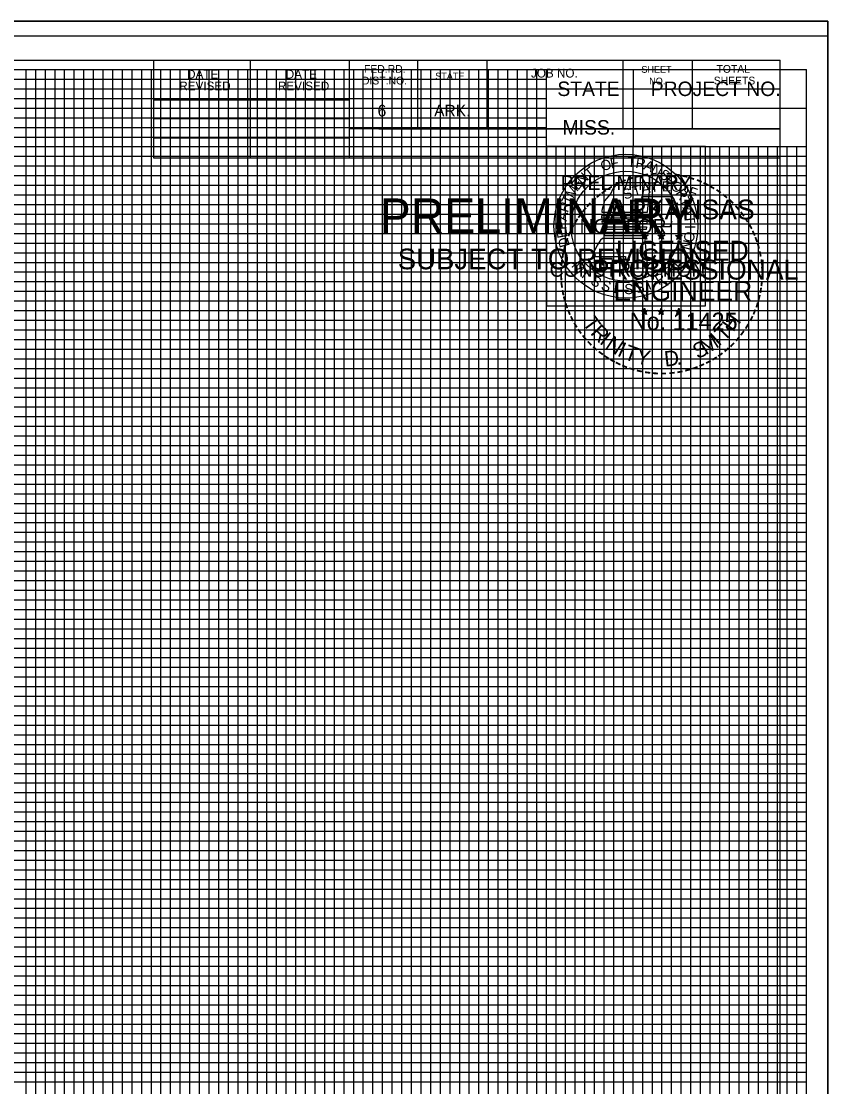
# Model space of a CAD drawing. Extents: x -10 to 342, y -5 to 215.
import ezdxf

# ---------------------------------------------------------------- set-up
doc = ezdxf.new("R2010")
doc.units = 0
for name, color, linetype in [('R_Border', 7, 'Continuous'), ('R_Border PE', 7, 'Continuous'), ('R_Border Prem', 7, 'Continuous'), ('R_No Plot', 7, 'Continuous'), ('SHEET_BORDER', 7, 'Continuous'), ('SHEET_LOGO', 7, 'Continuous'), ('SHEET_PLOTTING_SHAPE', 7, 'Continuous'), ('SHEET_PRELIM', 7, 'Continuous'), ('SHEET_PROJ_NUMBER', 7, 'Continuous'), ('XS_SHEET_MAJOR_GRIDS', 7, 'Continuous'), ('XS_SHEET_MEDIUM_GRIDS', 7, 'Continuous'), ('XS_SHEET_MINOR_GRIDS', 7, 'Continuous')]:
    doc.layers.add(name, color=color, linetype=linetype)

msp = doc.modelspace()

# ---------------------------------------------------------------- linework, layer by layer
at = {"layer": 'R_Border'}
for p, q in [((9.08, 210.98), (337.27, 210.98)), ((272.25, 200.79), (272.25, 210.98)), ((282.3, 200.79), (282.3, 210.98)), ((292.53, 210.98), (292.53, 200.79)), ((299.63, 210.98), (299.63, 203.83)), ((306.83, 210.98), (306.83, 203.83)), ((320.93, 210.98), (320.93, 203.83)), ((328.13, 210.98), (328.13, 203.83)), ((337.27, -0.89), (337.27, 210.98)), ((337.27, 207.95), (292.53, 207.95)), ((337.27, 207.97), (337.27, 207.97)), ((272.25, 206.84), (292.53, 206.84)), ((272.25, 204.92), (292.53, 204.92)), ((337.27, 203.83), (292.53, 203.83)), ((295.6, 203.83), (337.27, 203.83)), ((272.25, 202.92), (292.53, 202.92)), ((337.27, 200.79), (272.25, 200.79))]:
    msp.add_line(p, q, dxfattribs=at)
at = {"layer": 'R_Border PE'}
for p, q in [((322.82, 192.81), (323.18, 192.69)), ((322.82, 192.81), (323.09, 192.76)), ((322.82, 192.81), (323.07, 192.68)), ((322.96, 192.39), (323.18, 192.69)), ((322.96, 192.39), (323.09, 192.64)), ((322.96, 192.39), (323.18, 192.61)), ((323.18, 193.07), (323.14, 192.81)), ((323.18, 192.69), (323.18, 193.07)), ((323.18, 193.07), (323.24, 192.81)), ((323.55, 192.81), (323.18, 192.69)), ((323.41, 192.39), (323.18, 192.69)), ((323.41, 192.39), (323.18, 192.61)), ((323.55, 192.81), (323.25, 192.76)), ((323.41, 192.39), (323.26, 192.69)), ((323.55, 192.81), (323.33, 192.7)), ((324.56, 192.81), (324.92, 192.69)), ((324.56, 192.81), (324.82, 192.76)), ((324.56, 192.81), (324.8, 192.68)), ((324.69, 192.39), (324.92, 192.69)), ((324.69, 192.39), (324.82, 192.64)), ((324.69, 192.39), (324.92, 192.61)), ((324.92, 193.07), (324.88, 192.81)), ((324.92, 192.69), (324.92, 193.07)), ((324.92, 193.07), (324.97, 192.81)), ((325.28, 192.81), (324.92, 192.69)), ((325.14, 192.39), (324.92, 192.69)), ((325.14, 192.39), (324.92, 192.61)), ((325.28, 192.81), (324.98, 192.76)), ((325.14, 192.39), (325, 192.69)), ((325.28, 192.81), (325.07, 192.7)), ((326.39, 192.8), (326.75, 192.68)), ((326.39, 192.8), (326.65, 192.75)), ((326.39, 192.8), (326.63, 192.67)), ((326.53, 192.38), (326.75, 192.68)), ((326.53, 192.38), (326.66, 192.63)), ((326.53, 192.38), (326.75, 192.6)), ((326.75, 193.06), (326.71, 192.8)), ((326.75, 192.68), (326.75, 193.06)), ((326.75, 193.06), (326.8, 192.8)), ((327.11, 192.8), (326.75, 192.68)), ((326.97, 192.38), (326.75, 192.68)), ((326.97, 192.38), (326.75, 192.6)), ((327.11, 192.8), (326.81, 192.75)), ((326.97, 192.38), (326.83, 192.68)), ((327.11, 192.8), (326.9, 192.69)), ((322.82, 185), (323.18, 184.88)), ((322.82, 185), (323.08, 184.95)), ((322.82, 185), (323.06, 184.87)), ((322.96, 184.58), (323.18, 184.88)), ((322.96, 184.58), (323.09, 184.83)), ((322.96, 184.58), (323.18, 184.8)), ((323.18, 185.26), (323.14, 185)), ((323.18, 184.88), (323.18, 185.26)), ((323.18, 185.26), (323.23, 185)), ((323.54, 185), (323.18, 184.88)), ((323.4, 184.58), (323.18, 184.88)), ((323.4, 184.58), (323.18, 184.8)), ((323.54, 185), (323.24, 184.95)), ((323.4, 184.58), (323.26, 184.88)), ((323.54, 185), (323.33, 184.89)), ((324.55, 185), (324.91, 184.88)), ((324.55, 185), (324.81, 184.95)), ((324.55, 185), (324.8, 184.87)), ((324.69, 184.58), (324.91, 184.88)), ((324.69, 184.58), (324.82, 184.83)), ((324.69, 184.58), (324.91, 184.8)), ((324.91, 185.26), (324.87, 185)), ((324.91, 184.88), (324.91, 185.26)), ((324.91, 185.26), (324.96, 185)), ((325.27, 185), (324.91, 184.88)), ((325.13, 184.58), (324.91, 184.88)), ((325.13, 184.58), (324.91, 184.8)), ((325.27, 185), (324.98, 184.95)), ((325.13, 184.58), (324.99, 184.88)), ((325.27, 185), (325.06, 184.89)), ((326.39, 184.99), (326.75, 184.87)), ((326.39, 184.99), (326.65, 184.94)), ((326.39, 184.99), (326.63, 184.86)), ((326.52, 184.57), (326.75, 184.87)), ((326.52, 184.57), (326.65, 184.82)), ((326.52, 184.57), (326.75, 184.79)), ((326.75, 185.25), (326.7, 184.99)), ((326.75, 184.87), (326.75, 185.25)), ((326.75, 185.25), (326.8, 184.99)), ((327.11, 184.99), (326.75, 184.87)), ((326.97, 184.57), (326.75, 184.87)), ((326.97, 184.57), (326.75, 184.79)), ((327.11, 184.99), (326.81, 184.94)), ((326.97, 184.57), (326.83, 184.87)), ((327.11, 184.99), (326.9, 184.88))]:
    msp.add_line(p, q, dxfattribs=at)
for points in [[(322.87, 196.81), (323.14, 195.95)], [(326.51, 195.86), (326.66, 196.15), (325.95, 196.12), (326.1, 196.81), (322.87, 196.81)], [(323.38, 194.31), (323.38, 194.22), (323.96, 194.2), (323.9, 193.71), (325.85, 193.71), (326.05, 194.26)], [(323.18, 193.07), (323.41, 192.39), (322.82, 192.81), (323.55, 192.81), (322.96, 192.39), (323.18, 193.07)], [(324.92, 193.07), (325.14, 192.39), (324.56, 192.81), (325.28, 192.81), (324.69, 192.39), (324.92, 193.07)], [(326.75, 193.06), (326.97, 192.38), (326.39, 192.8), (327.11, 192.8), (326.53, 192.38), (326.75, 193.06)], [(323.18, 185.26), (323.4, 184.58), (322.82, 185), (323.54, 185), (322.96, 184.58), (323.18, 185.26)], [(324.91, 185.26), (325.13, 184.58), (324.55, 185), (325.27, 185), (324.69, 184.58), (324.91, 185.26)], [(326.75, 185.25), (326.97, 184.57), (326.39, 184.99), (327.11, 184.99), (326.52, 184.57), (326.75, 185.25)]]:
    msp.add_lwpolyline(points, dxfattribs=at)
for centre, major_axis in [((323.18, 192.69), (0.179, 0)), ((323.18, 192.69), (0.15, 0)), ((323.18, 192.69), (0.12, 0)), ((323.18, 192.69), (0.103, 0)), ((323.18, 192.69), (0.0776, 0)), ((323.18, 192.69), (0.0514, 0)), ((323.18, 192.69), (0.0308, 0)), ((324.92, 192.69), (0.179, 0)), ((324.92, 192.69), (0.15, 0)), ((324.92, 192.69), (0.12, 0)), ((324.92, 192.69), (0.103, 0)), ((324.92, 192.69), (0.0776, 0)), ((324.92, 192.69), (0.0514, 0)), ((324.92, 192.69), (0.0308, 0)), ((326.75, 192.68), (0.179, 0)), ((326.75, 192.68), (0.15, 0)), ((326.75, 192.68), (0.12, 0)), ((326.75, 192.68), (0.103, 0)), ((326.75, 192.68), (0.0776, 0)), ((326.75, 192.68), (0.0514, 0)), ((326.75, 192.68), (0.0308, 0)), ((323.18, 184.88), (0.179, 0)), ((323.18, 184.88), (0.15, 0)), ((323.18, 184.88), (0.12, 0)), ((323.18, 184.88), (0.103, 0)), ((323.18, 184.88), (0.0776, 0)), ((323.18, 184.88), (0.0514, 0)), ((323.18, 184.88), (0.0308, 0)), ((324.91, 184.88), (0.179, 0)), ((324.91, 184.88), (0.15, 0)), ((324.91, 184.88), (0.12, 0)), ((324.91, 184.88), (0.103, 0)), ((324.91, 184.88), (0.0776, 0)), ((324.91, 184.88), (0.0514, 0)), ((324.91, 184.88), (0.0308, 0)), ((326.75, 184.87), (0.179, 0)), ((326.75, 184.87), (0.15, 0)), ((326.75, 184.87), (0.12, 0)), ((326.75, 184.87), (0.103, 0)), ((326.75, 184.87), (0.0776, 0)), ((326.75, 184.87), (0.0514, 0)), ((326.75, 184.87), (0.0308, 0))]:
    msp.add_ellipse(centre, major_axis=major_axis, ratio=0.993497, dxfattribs=at)
at = {"layer": 'R_No Plot'}
for p, q in [((-3.79, 215), (342.2, 215)), ((312.39, 177.64), (312.39, 177.64))]:
    msp.add_line(p, q, dxfattribs=at)
msp.add_lwpolyline([(-3.8, 215), (342.2, 215), (342.2, -5), (-3.8, -5)], close=True, dxfattribs=at)
at = {"layer": 'SHEET_BORDER'}
for p, q in [((-9.8, 213.5), (342.2, 213.5)), ((5, 210), (340, 210)), ((340, 0), (340, 210)), ((313, 206), (340, 206)), ((329.5, 202), (329.5, 202))]:
    msp.add_line(p, q, dxfattribs=at)
at = {"layer": 'SHEET_LOGO'}
for points in [[(313, 185.5), (329.5, 185.5), (329.5, 202), (313, 202)], [(323.76, 198.09), (323.62, 198.12), (323.61, 198.23), (320.22, 198.23), (320.25, 198.07), (319.85, 197.55), (319.68, 197.13), (319.04, 196.37), (318.76, 195.37), (318.76, 195.19), (323.51, 195.19)], [(318.77, 194.87), (323.49, 194.87), (323.45, 194.59), (318.77, 194.59)], [(318.79, 194.28), (323.42, 194.28), (323.42, 194.01), (318.83, 194.01)], [(323.38, 193.67), (323.36, 193.4), (319, 193.4), (318.88, 193.69)], [(318.83, 192.49), (318.63, 192.3), (318.27, 191.77), (317.92, 191.05), (318.08, 190.78), (317.99, 190.59), (321.21, 190.59), (321.22, 190.43), (321.06, 190.26), (321.02, 190), (321.21, 189.7), (321.43, 189.11), (321.65, 189.08), (321.93, 189.31), (322.5, 189.48), (322.81, 189.38), (323.54, 189.43), (323.26, 192.34), (323.28, 192.49)], [(319.15, 193.08), (319.15, 193.05), (319, 192.89), (318.98, 192.8), (323.3, 192.8), (323.33, 193.08)]]:
    msp.add_lwpolyline(points, close=True, dxfattribs=at)
for radius in [7.46, 5.7]:
    msp.add_circle((321.25, 193.75), radius, dxfattribs=at)
at = {"layer": 'SHEET_PLOTTING_SHAPE'}
msp.add_lwpolyline([(-3.8, -5), (342.2, -5), (342.2, 215), (-3.8, 215)], close=True, dxfattribs=at)
at = {"layer": 'SHEET_PRELIM'}
msp.add_lwpolyline([(313, 185.5), (329.5, 185.5), (329.5, 202), (313, 202)], close=True, dxfattribs=at)
at = {"layer": 'SHEET_PROJ_NUMBER'}
for p, q in [((313, 202), (313, 210)), ((322, 210), (322, 202)), ((313, 202), (340, 202))]:
    msp.add_line(p, q, dxfattribs=at)
at = {"layer": 'XS_SHEET_MAJOR_GRIDS'}
for p, q in [((260, 0), (260, 210)), ((270, 0), (270, 210)), ((280, 0), (280, 210)), ((290, 0), (290, 210)), ((300, 0), (300, 210)), ((310, 0), (310, 210)), ((320, 0), (320, 202)), ((330, 0), (330, 202)), ((5, 200), (340, 200)), ((5, 190), (340, 190)), ((5, 180), (340, 180)), ((5, 170), (340, 170)), ((5, 160), (340, 160)), ((5, 150), (340, 150)), ((5, 140), (340, 140)), ((5, 130), (340, 130)), ((5, 120), (340, 120)), ((5, 110), (340, 110))]:
    msp.add_line(p, q, dxfattribs=at)
at = {"layer": 'XS_SHEET_MEDIUM_GRIDS'}
for p, q in [((265, 0), (265, 210)), ((275, 0), (275, 210)), ((285, 0), (285, 210)), ((295, 0), (295, 210)), ((305, 0), (305, 210)), ((5, 205), (313, 205)), ((315, 0), (315, 202)), ((325, 0), (325, 202)), ((335, 10), (335, 202)), ((5, 195), (340, 195)), ((5, 185), (340, 185)), ((5, 175), (340, 175)), ((5, 165), (340, 165)), ((5, 155), (340, 155)), ((5, 145), (340, 145)), ((5, 135), (340, 135)), ((5, 125), (340, 125)), ((5, 115), (340, 115)), ((5, 105), (340, 105))]:
    msp.add_line(p, q, dxfattribs=at)
at = {"layer": 'XS_SHEET_MINOR_GRIDS'}
for p, q in [((259, 0), (259, 210)), ((261, 0), (261, 210)), ((262, 0), (262, 210)), ((263, 0), (263, 210)), ((264, 0), (264, 210)), ((266, 0), (266, 210)), ((267, 0), (267, 210)), ((268, 0), (268, 210)), ((269, 0), (269, 210)), ((271, 0), (271, 210)), ((272, 0), (272, 210)), ((273, 0), (273, 210)), ((274, 0), (274, 210)), ((276, 0), (276, 210)), ((277, 0), (277, 210)), ((278, 0), (278, 210)), ((279, 0), (279, 210)), ((281, 0), (281, 210)), ((282, 0), (282, 210)), ((283, 0), (283, 210)), ((284, 0), (284, 210)), ((286, 0), (286, 210)), ((287, 0), (287, 210)), ((288, 0), (288, 210)), ((289, 0), (289, 210)), ((291, 0), (291, 210)), ((292, 0), (292, 210)), ((293, 0), (293, 210)), ((294, 0), (294, 210)), ((296, 0), (296, 210)), ((297, 0), (297, 210)), ((298, 0), (298, 210)), ((299, 0), (299, 210)), ((301, 0), (301, 210)), ((302, 0), (302, 210)), ((303, 0), (303, 210)), ((304, 0), (304, 210)), ((306, 0), (306, 210)), ((307, 0), (307, 210)), ((308, 0), (308, 210)), ((309, 0), (309, 210)), ((311, 0), (311, 210)), ((312, 0), (312, 210)), ((5, 209), (313, 209)), ((5, 208), (313, 208)), ((5, 207), (313, 207)), ((5, 206), (313, 206)), ((5, 204), (313, 204)), ((5, 203), (313, 203)), ((5, 202), (313, 202)), ((313, 0), (313, 202)), ((314, 0), (314, 202)), ((316, 0), (316, 202)), ((317, 0), (317, 202)), ((318, 0), (318, 202)), ((319, 0), (319, 202)), ((321, 0), (321, 202)), ((322, 0), (322, 202)), ((323, 0), (323, 202)), ((324, 0), (324, 202)), ((326, 0), (326, 202)), ((327, 0), (327, 202)), ((328, 0), (328, 202)), ((329, 0), (329, 202)), ((331, 10), (331, 202)), ((332, 10), (332, 202)), ((333, 10), (333, 202)), ((334, 10), (334, 202)), ((336, 10), (336, 202)), ((337, 10), (337, 202)), ((338, 10), (338, 202)), ((339, 10), (339, 202)), ((5, 201), (340, 201)), ((5, 199), (340, 199)), ((5, 198), (340, 198)), ((5, 197), (340, 197)), ((5, 196), (340, 196)), ((5, 194), (340, 194)), ((5, 193), (340, 193)), ((5, 192), (340, 192)), ((5, 191), (340, 191)), ((5, 189), (340, 189)), ((5, 188), (340, 188)), ((5, 187), (340, 187)), ((5, 186), (340, 186)), ((5, 184), (340, 184)), ((5, 183), (340, 183)), ((5, 182), (340, 182)), ((5, 181), (340, 181)), ((5, 179), (340, 179)), ((5, 178), (340, 178)), ((5, 177), (340, 177)), ((5, 176), (340, 176)), ((5, 174), (340, 174)), ((5, 173), (340, 173)), ((5, 172), (340, 172)), ((5, 171), (340, 171)), ((5, 169), (340, 169)), ((5, 168), (340, 168)), ((5, 167), (340, 167)), ((5, 166), (340, 166)), ((5, 164), (340, 164)), ((5, 163), (340, 163)), ((5, 162), (340, 162)), ((5, 161), (340, 161)), ((5, 159), (340, 159)), ((5, 158), (340, 158)), ((5, 157), (340, 157)), ((5, 156), (340, 156)), ((5, 154), (340, 154)), ((5, 153), (340, 153)), ((5, 152), (340, 152)), ((5, 151), (340, 151)), ((5, 149), (340, 149)), ((5, 148), (340, 148)), ((5, 147), (340, 147)), ((5, 146), (340, 146)), ((5, 144), (340, 144)), ((5, 143), (340, 143)), ((5, 142), (340, 142)), ((5, 141), (340, 141)), ((5, 139), (340, 139)), ((5, 138), (340, 138)), ((5, 137), (340, 137)), ((5, 136), (340, 136)), ((5, 134), (340, 134)), ((5, 133), (340, 133)), ((5, 132), (340, 132)), ((5, 131), (340, 131)), ((5, 129), (340, 129)), ((5, 128), (340, 128)), ((5, 127), (340, 127)), ((5, 126), (340, 126)), ((5, 124), (340, 124)), ((5, 123), (340, 123)), ((5, 122), (340, 122)), ((5, 121), (340, 121)), ((5, 119), (340, 119)), ((5, 118), (340, 118)), ((5, 117), (340, 117)), ((5, 116), (340, 116)), ((5, 114), (340, 114)), ((5, 113), (340, 113)), ((5, 112), (340, 112)), ((5, 111), (340, 111)), ((5, 109), (340, 109)), ((5, 108), (340, 108)), ((5, 107), (340, 107)), ((5, 106), (340, 106))]:
    msp.add_line(p, q, dxfattribs=at)

# ---------------------------------------------------------------- texts
at = {"layer": 'R_Border'}
for s, height, p in [('DATE', 0.907, (275.71, 209.06)), ('DATE', 0.907, (285.95, 209.06)), ('FED.RD.', 0.806, (294.07, 209.66)), ('JOB NO.', 0.907, (311.4, 209.17)), ('SHEET', 0.705, (322.86, 209.66)), ('TOTAL', 0.806, (330.66, 209.66)), ('DIST.NO.', 0.806, (293.86, 208.45)), ('STATE', 0.705, (301.46, 208.96)), ('NO.', 0.705, (323.67, 208.45)), ('SHEETS', 0.806, (330.37, 208.45)), ('REVISED', 0.907, (274.9, 207.84)), ('REVISED', 0.907, (285.14, 207.84)), ('6', 1.21, (295.48, 205.13)), ('ARK.', 1.209, (301.35, 205.13))]:
    msp.add_text(s, height=height, dxfattribs=at).set_placement(p)
at = {"layer": 'R_Border PE'}
for s, height, rotation, p in [('-', 1.65, 13.5448, (322.34, 198.22)), ('-', 1.65, 10.1543, (323.05, 198.39)), ('-', 1.65, 5.8587, (323.8, 198.5)), ('-', 1.65, 0.185, (324.61, 198.57)), ('-', 1.65, 357.7577, (325.36, 198.56)), ('-', 1.65, 352.2121, (326.13, 198.5)), ('-', 1.65, 347.2854, (326.87, 198.38)), ('-', 1.65, 33.8903, (319.63, 196.98)), ('-', 1.65, 28.6343, (320.25, 197.37)), ('-', 1.65, 24.1673, (320.91, 197.69)), ('-', 1.65, 19.0604, (321.57, 197.97)), ('T', 1.03, 16.3026, (322.11, 196.82)), ('A', 1.03, 11.1421, (322.96, 197.08)), ('T', 1.03, 5.9839, (323.84, 197.25)), ('E', 1.03, 0.8269, (324.99, 197.36)), ('O', 1.03, 350.5125, (326.66, 197.14)), ('F', 1.03, 340.1901, (327.65, 196.91)), ('-', 1.65, 342.444, (327.53, 198.22)), ('-', 1.65, 337.9853, (328.3, 197.99)), ('-', 1.65, 334.2676, (328.95, 197.71)), ('-', 1.65, 329.8037, (329.55, 197.42)), ('-', 1.65, 42.7759, (318.09, 195.76)), ('-', 1.65, 38.768, (318.54, 196.19)), ('-', 1.65, 36.0537, (319.03, 196.58)), ('S', 1.03, 21.4664, (321.16, 196.48)), ('-', 1.65, 326.0361, (330.22, 197.05)), ('-', 1.65, 320.713, (330.85, 196.61)), ('-', 1.66, 50.4307, (317.2, 194.76)), ('-', 1.66, 48.2374, (317.62, 195.26)), ('-', 1.66, 315.7654, (331.48, 196.11)), ('-', 1.66, 310.0638, (332.07, 195.54)), ('-', 1.66, 57.9026, (316.44, 193.63)), ('-', 1.66, 54.055, (316.78, 194.18)), ('-', 1.66, 306.8314, (332.61, 194.92)), ('-', 1.45, 303.848, (333.12, 194.33)), ('-', 1.66, 62.7194, (316.11, 193)), ('-', 1.66, 299.8294, (333.45, 193.71)), ('-', 1.66, 72.2864, (315.62, 191.72)), ('-', 1.66, 67.6431, (315.84, 192.37)), ('-', 1.66, 294.8048, (333.78, 193.08)), ('-', 1.66, 290.6961, (334.05, 192.48)), ('-', 1.66, 75.3699, (315.41, 190.98)), ('-', 1.66, 285.2177, (334.29, 191.88)), ('-', 1.66, 85.155, (315.2, 189.54)), ('-', 1.66, 81.1446, (315.28, 190.25)), ('-', 1.66, 280.6168, (334.5, 191.12)), ('-', 1.66, 276.6389, (334.67, 190.33)), ('-', 1.66, 89.0561, (315.17, 188.81)), ('-', 1.66, 274.3583, (334.73, 189.58)), ('-', 1.66, 94.2232, (315.21, 188.07)), ('-', 1.66, 99.0055, (315.28, 187.38)), ('-', 1.66, 263.4751, (334.75, 188.24)), ('-', 1.66, 269.9403, (334.77, 188.93)), ('-', 1.66, 101.7895, (315.42, 186.62)), ('-', 1.66, 260.9373, (334.67, 187.57)), ('-', 1.66, 105.5541, (315.59, 186.01)), ('-', 1.66, 109.2032, (315.81, 185.36)), ('-', 1.66, 252.7626, (334.37, 186.13)), ('-', 1.66, 255.6732, (334.56, 186.87)), ('-', 1.66, 114.2038, (316.08, 184.74)), ('T', 1.59, 306.2186, (316.7, 183.69)), ('H', 1.6, 54.4322, (332.4, 182.69)), ('-', 1.66, 247.758, (334.14, 185.43)), ('-', 1.66, 115.8753, (316.39, 184.11)), ('-', 1.66, 120.6107, (316.76, 183.5)), ('R', 1.59, 314.1918, (317.49, 182.61)), ('T', 1.59, 46.4578, (331.47, 181.72)), ('-', 1.66, 238.9062, (333.46, 184.01)), ('-', 1.66, 244.4747, (333.87, 184.79)), ('-', 1.66, 126.0712, (317.18, 182.92)), ('-', 1.66, 130.903, (317.66, 182.35)), ('I', 1.59, 322.1506, (318.43, 181.64)), ('N', 1.59, 326.672, (319.02, 181.16)), ('M', 1.59, 32.4867, (329.56, 180.35)), ('I', 1.59, 41.9277, (330.89, 181.23)), ('-', 1.66, 231.0712, (332.59, 182.75)), ('-', 1.66, 233.667, (333.04, 183.34)), ('-', 1.66, 134.4107, (318.2, 181.79)), ('-', 1.65, 139.1189, (318.74, 181.31)), ('I', 1.59, 335.5017, (320.27, 180.35)), ('T', 1.59, 340.0116, (320.96, 180.01)), ('S', 1.59, 26.7805, (328.69, 179.93)), ('-', 1.66, 225.5785, (332.1, 182.17)), ('-', 1.65, 144.8226, (319.32, 180.9)), ('-', 1.65, 148.2573, (319.9, 180.51)), ('Y', 1.59, 347.9322, (322.22, 179.55)), ('D', 1.59, 6.3556, (325.32, 179.18)), ('-', 1.65, 212.0806, (330.43, 180.76)), ('-', 1.65, 215.5593, (330.99, 181.16)), ('-', 1.65, 220.9, (331.56, 181.65)), ('-', 1.65, 151.7266, (320.5, 180.18)), ('-', 1.65, 154.7447, (321.05, 179.92)), ('-', 1.65, 158.6881, (321.69, 179.66)), ('-', 1.65, 162.9036, (322.41, 179.44)), ('.', 1.59, 13.678, (326.56, 179.31)), ('-', 1.65, 200.595, (328.56, 179.79)), ('-', 1.65, 204.1119, (329.2, 180.07)), ('-', 1.65, 207.2046, (329.85, 180.4)), ('-', 1.65, 167.6339, (323.15, 179.27)), ('-', 1.65, 173.1598, (323.95, 179.16)), ('-', 1.65, 176.5409, (324.73, 179.1)), ('-', 1.65, 181.5814, (325.5, 179.12)), ('-', 1.65, 185.7791, (326.34, 179.2)), ('-', 1.65, 191.2142, (327.1, 179.34)), ('-', 1.65, 195.3784, (327.86, 179.54))]:
    msp.add_text(s, height=height, rotation=rotation, dxfattribs=at).set_placement(p)
for s, height, p in [('ARKANSAS', 2.062, (319.6, 194.45)), ('DWB', 0.0103, (323.17, 192.69)), ('DWB', 0.0103, (324.9, 192.69)), ('DWB', 0.0103, (326.74, 192.68)), ('LICENSED', 2.062, (320.22, 190.17)), ('PROFESSIONAL', 2.0625, (317.7, 188.21)), ('ENGINEER', 2.062, (319.97, 186.01)), ('No. 11425', 1.812, (321.66, 182.97)), ('DWB', 0.0103, (323.17, 184.88)), ('DWB', 0.0103, (324.9, 184.88)), ('DWB', 0.0103, (326.73, 184.87))]:
    msp.add_text(s, height=height, dxfattribs=at).set_placement(p)
at = {"layer": 'R_Border Prem'}
for s, height, p in [('PRELIMINARY', 3.6093, (295.7, 193.02)), ('DWB', 0.0103, (296.47, 194.93)), ('SUBJECT TO REVISION', 2.1399, (297.57, 189.28))]:
    msp.add_text(s, height=height, dxfattribs=at).set_placement(p)
at = {"layer": 'SHEET_LOGO'}
for s, rotation, p in [('O', 18.1879, (318.82, 199.43)), ('F', 11.3901, (319.73, 199.71)), ('T', 357.7944, (321.39, 199.89)), ('R', 350.9966, (322.2, 199.82)), ('A', 337.4009, (323.02, 199.68)), ('N', 330.6031, (323.76, 199.38)), ('N', 45.3792, (316.78, 197.95)), ('T', 38.5814, (317.48, 198.6)), ('S', 323.8053, (324.6, 198.91)), ('P', 317.0075, (325.23, 198.43)), ('M', 58.9749, (315.78, 196.57)), ('E', 52.1771, (316.3, 197.41)), ('O', 310.2096, (325.78, 197.91)), ('T', 65.7727, (315.49, 195.91)), ('R', 303.4118, (326.34, 197.18)), ('T', 296.614, (326.78, 196.44)), ('R', 72.5705, (315.23, 195.1)), ('A', 283.0183, (327.11, 195.7)), ('A', 79.3684, (315.09, 194.23)), ('T', 276.2205, (327.31, 194.83)), ('P', 92.964, (315.11, 193.4)), ('E', 99.7618, (315.22, 192.61)), ('I', 269.4227, (327.4, 193.87)), ('D', 106.5597, (315.45, 191.73)), ('N', 255.827, (327.25, 192.42)), ('O', 262.6248, (327.38, 193.26)), ('M', 309.1102, (315.54, 189.62)), ('I', 48.9775, (326.71, 189.29)), ('I', 321.5936, (316.55, 188.5)), ('P', 42.7358, (325.72, 188.3)), ('S', 327.8353, (317.49, 187.81)), ('S', 340.3187, (318.59, 187.22)), ('I', 352.8022, (319.91, 186.83)), ('S', 11.5273, (322.33, 186.78)), ('I', 24.0107, (323.65, 187.11)), ('P', 30.2524, (324.67, 187.6)), ('S', 359.0439, (321.07, 186.71))]:
    msp.add_text(s, height=1.06, rotation=rotation, dxfattribs=at).set_placement(p)
at = {"layer": 'SHEET_PRELIM'}
for s, p in [('PRELIMINARY', (314.48, 197.5)), ('NOT FOR', (316.45, 193)), ('CONSTRUCTION', (313.34, 188.5))]:
    msp.add_text(s, height=1.5, dxfattribs=at).set_placement(p)
at = {"layer": 'SHEET_PROJ_NUMBER'}
for s, p in [('STATE', (314.14, 207.25)), ('PROJECT NO.', (323.83, 207.25)), ('MISS.', (314.68, 203.25))]:
    msp.add_text(s, height=1.5, dxfattribs=at).set_placement(p)

doc.saveas('drawing.dxf')
